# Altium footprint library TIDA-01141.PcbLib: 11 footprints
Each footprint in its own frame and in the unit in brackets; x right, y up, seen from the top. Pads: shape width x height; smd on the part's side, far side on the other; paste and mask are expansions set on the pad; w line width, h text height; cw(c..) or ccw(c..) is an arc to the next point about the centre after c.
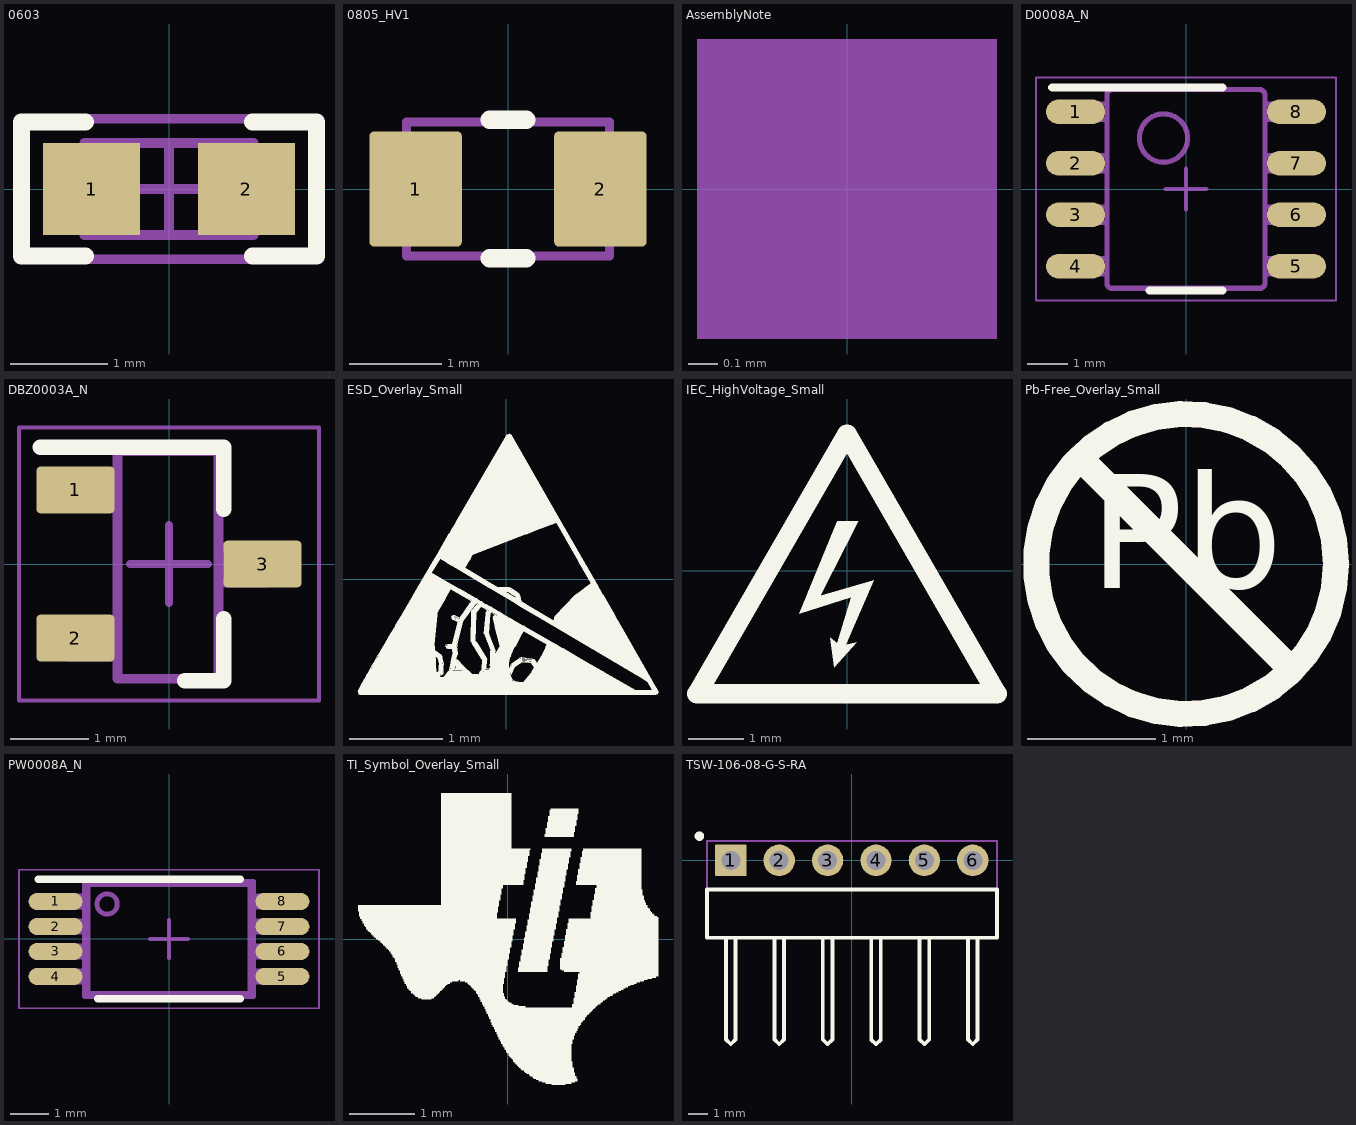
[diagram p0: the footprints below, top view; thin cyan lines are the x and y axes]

## 0603 [mm] "0603 from SM-752 data"
height 1
pads (2):
  rect 1x0.95 smd: 1(-0.8,0) 2(0.8,0)
Top Overlay:
  lines w0.178: -0.864,-0.691 -1.524,-0.691 -1.524,0.693 -0.864,0.693 ; 0.864,-0.691 1.524,-0.691 1.524,0.693 0.864,0.693
Mechanical 5:
  lines w0.1: -1.55,-0.725 -1.55,0.725 1.55,0.725 1.55,-0.725 -1.55,-0.725
  text ".Designator" at -0.559,-0.356 h0.76
Mechanical 13:
  lines w0.1: -0.55,-0.475 -0.55,0.475 ; 0.55,-0.475 0.55,0.475 ; -0.875,-0.475 0.875,-0.475 0.875,0.475 -0.875,0.475 -0.875,-0.475
Mechanical 15:
  lines w0.1: -0.475,0 0.475,0 ; 0,-0.475 0,0.475 ; -1.55,-0.725 1.55,-0.725 1.55,0.725 -1.55,0.725 -1.55,-0.725
3D body: height 1, standoff 0, extent -0.874,-0.474 -0.551,0.474
3D body: height 1, standoff 0, extent -0.549,-0.474 0.549,0.474
3D body: height 1, standoff 0, extent 0.551,-0.474 0.874,0.474

## 0805_HV1 [mm] "Custom footprint based on analyzing multiple manufacturer recommendations"
height 1.45
pads (2):
  rrect10% 1x1.25 smd: 1(-1,0) 2(1,0)
Top Overlay:
  lines w0.2: -0.2,-0.75 0.2,-0.75 ; -0.2,0.75 0.2,0.75
Mechanical 5:
  lines w0.1: -1.1,-0.725 1.1,-0.725 1.1,0.725 -1.1,0.725 -1.1,-0.725
  text ".Designator" at -0.737,-0.381 h0.76
3D body: height 1.45, standoff 0, extent -1.1,-0.725 1.1,0.725

## AssemblyNote [mm] "Assembly Note"
Mechanical 5:
  rectangle: -0.508,-0.508 0.508,0.508
  text ".Designator" at -4.191,-0.508 h1.02
  text ".Comment" at 1.143,-0.508 h1.02

## D0008A_N [mm] "SOIC, 8-Leads, Body 4.9x3.9mm, Pitch 1.27mm, IPC Medium Density"
height 1.75
pads (8):
  oval 1.45x0.6 smd: 1(-2.725,1.905) 2(-2.725,0.635) 3(-2.725,-0.635) 4(-2.725,-1.905) 5(2.725,-1.905) 6(2.725,-0.635) 7(2.725,0.635) 8(2.725,1.905)
Top Overlay:
  lines w0.2: -3.3,2.5 0.9,2.5 ; -0.9,-2.5 0.9,-2.5
Mechanical 5:
  lines w0.127: -2.375,-2.095 -1.995,-2.095 -1.952,-2.095 -1.952,-1.715 -1.995,-1.715 -2.375,-1.715 ; -2.375,-2.095 -2.589,-2.095 -3.002,-2.095 -3.002,-1.715 -2.589,-1.715 -2.375,-1.715 ; -2.375,-2.095 -2.375,-1.715 ; -2.375,-0.825 -1.995,-0.825 -1.952,-0.825 -1.952,-0.445 -1.995,-0.445 -2.375,-0.445 ; -2.375,-0.825 -2.589,-0.825 -3.002,-0.825 -3.002,-0.445 -2.589,-0.445 -2.375,-0.445 ; -2.375,-0.825 -2.375,-0.445 ; -2.375,0.445 -1.995,0.445 -1.952,0.445 -1.952,0.825 -1.995,0.825 -2.375,0.825 ; -2.375,0.445 -2.589,0.445 -3.002,0.445 -3.002,0.825 -2.589,0.825 -2.375,0.825 ; -2.375,0.445 -2.375,0.825 ; -2.375,1.715 -1.995,1.715 -1.952,1.715 -1.952,2.095 -1.995,2.095 -2.375,2.095 ; -2.375,1.715 -2.589,1.715 -3.002,1.715 -3.002,2.095 -2.589,2.095 -2.375,2.095 ; -2.375,1.715 -2.375,2.095 ; -0.332,-2.45 -1.825,-2.45 -1.826,-2.45 cw(c-1.825,-2.323) -1.952,-2.324 -1.952,-2.323 -1.952,2.323 -1.952,2.324 cw(c-1.825,2.323) -1.826,2.45 -1.825,2.45 -0.332,2.45 ; -0.332,-2.45 -0.182,-2.45 ; -0.332,-2.45 -0.182,-2.45 ; -0.332,2.45 -0.182,2.45 ; -0.332,2.45 -0.182,2.45 ; -0.182,-2.45 0.178,-2.45 ; -0.182,2.45 0.178,2.45 ; 0.178,-2.45 0.328,-2.45 ; 0.178,-2.45 0.328,-2.45 ; 0.178,2.45 0.328,2.45 ; 0.178,2.45 0.328,2.45 ; 0.328,-2.45 1.821,-2.45 1.822,-2.45 ccw(c1.821,-2.323) 1.948,-2.324 1.948,-2.323 1.948,2.323 1.948,2.324 ccw(c1.821,2.323) 1.822,2.45 1.821,2.45 0.328,2.45 ; 2.371,-2.095 2.585,-2.095 2.998,-2.095 2.998,-1.715 2.585,-1.715 2.371,-1.715 ; 2.371,-2.095 1.991,-2.095 1.948,-2.095 1.948,-1.715 1.991,-1.715 2.371,-1.715 ; 2.371,-2.095 2.371,-1.715 ; 2.371,-0.825 2.585,-0.825 2.998,-0.825 2.998,-0.445 2.585,-0.445 2.371,-0.445 ; 2.371,-0.825 1.991,-0.825 1.948,-0.825 1.948,-0.445 1.991,-0.445 2.371,-0.445 ; 2.371,-0.825 2.371,-0.445 ; 2.371,0.445 2.585,0.445 2.998,0.445 2.998,0.825 2.585,0.825 2.371,0.825 ; 2.371,0.445 1.991,0.445 1.948,0.445 1.948,0.825 1.991,0.825 2.371,0.825 ; 2.371,0.445 2.371,0.825 ; 2.371,1.715 2.585,1.715 2.998,1.715 2.998,2.095 2.585,2.095 2.371,2.095 ; 2.371,1.715 1.991,1.715 1.948,1.715 1.948,2.095 1.991,2.095 2.371,2.095 ; 2.371,1.715 2.371,2.095 ; -0.555,0.659 cw(c-0.555,1.256) -0.555,1.853 cw(c-0.555,1.256) -0.555,0.659
  text ".Designator" at 0.305,-1.27 h0.76
Mechanical 15:
  lines w0.05: -3.7,-2.75 3.7,-2.75 3.7,2.75 -3.7,2.75 -3.7,-2.75
  lines w0.1: -0.5,0 0.5,0 ; 0,-0.5 0,0.5
3D body: height 1.63, standoff 0, extent -3,-2.45 3,2.45

## DBZ0003A_N [mm] "SOT23, 3-Leads, Body 2.9x1.3mm, Pitch 0.95mm, Lead Span 2.4mm, IPC Medium Density"
height 1.12
pads (3):
  rrect17% 1x0.6 smd: 1(-1.2,0.95) 2(-1.2,-0.95) 3(1.2,0)
Top Overlay:
  lines w0.2: -1.651,1.5 0.7,1.5 0.7,0.7 ; 0.2,-1.5 0.7,-1.5 0.7,-0.7
Mechanical 5:
  lines w0.127: -1.27,-1.187 -1.27,-0.743 -1.063,-0.743 -1.005,-0.743 -0.814,-0.743 -0.66,-0.743 -0.66,-1.187 -0.814,-1.187 -1.005,-1.187 -1.063,-1.187 -1.27,-1.187 ; -1.27,0.718 -1.27,1.162 -1.063,1.162 -1.005,1.162 -0.814,1.162 -0.66,1.162 -0.66,0.718 -0.814,0.718 -1.005,0.718 -1.063,0.718 -1.27,0.718 ; -0.66,-1.473 -0.66,1.448 0.635,1.448 0.635,-1.473 -0.66,-1.473 ; 0.635,-0.235 0.789,-0.235 0.98,-0.235 1.037,-0.235 1.245,-0.235 1.245,0.21 1.037,0.21 0.98,0.21 0.789,0.21 0.635,0.21 0.635,-0.235
  text ".Designator" at -0.432,0.711 h0.76
Mechanical 15:
  lines w0.05: -1.925,-1.75 1.925,-1.75 1.925,1.75 -1.925,1.75 -1.925,-1.75
  lines w0.1: -0.5,0 0.5,0 ; 0,-0.5 0,0.5
3D body: height 0.98, standoff 0, extent -1.257,-1.461 1.258,1.461

## ESD_Overlay_Small [mm]
height 0.33
Top Overlay:
  drawing of 901 lines, arcs and shapes, not listed

## IEC_HighVoltage_Small [mm]
height 0.33
Top Overlay:
  region: -0.178,0.889 0.203,0.889 -0.483,-0.457 0.483,-0.178 -0.025,-1.346 0.178,-1.295 -0.229,-1.753 -0.305,-1.219 -0.178,-1.321 0.076,-0.483 -0.864,-0.787
  lines w0.356: -2.718,-2.235 0,2.472 2.718,-2.235 -2.718,-2.235

## Pb-Free_Overlay_Small [mm]
Top Overlay:
  circle w0.203: c0,0 r1.168
  lines w0.203: -0.826,0.826 0.826,-0.826
  text "Pb" at -0.752,-0.48 h1.52

## PW0008A_N [mm] "TSOP, 8-Leads, Body 3x4.4mm, Pitch 0.65mm, IPC Medium Density"
height 1.2
pads (8):
  oval 1.4x0.45 smd: 1(-2.95,0.975) 2(-2.95,0.325) 3(-2.95,-0.325) 4(-2.95,-0.975) 5(2.95,-0.975) 6(2.95,-0.325) 7(2.95,0.325) 8(2.95,0.975)
Top Overlay:
  lines w0.2: -3.4,1.55 1.85,1.55 ; -1.85,-1.55 1.85,-1.55
Mechanical 5:
  lines w0.127: -2.2,-1.5 -2.2,-1.125 ; -2.2,-1.5 2.2,-1.5 ; -2.2,-1.5 -2.11,-1.41 ; -2.2,-1.125 -2.4,-1.125 -2.669,-1.125 -2.785,-1.125 -2.856,-1.125 -3.228,-1.125 -3.228,-0.825 -2.856,-0.825 -2.785,-0.825 -2.669,-0.825 -2.4,-0.825 -2.2,-0.825 ; -2.2,-1.125 -2.2,-0.825 ; -2.2,-0.825 -2.2,-0.475 ; -2.2,-0.475 -2.2,-0.175 ; -2.2,-0.475 -2.4,-0.475 -2.669,-0.475 -2.785,-0.475 -2.856,-0.475 -3.228,-0.475 -3.228,-0.175 -2.856,-0.175 -2.785,-0.175 -2.669,-0.175 -2.4,-0.175 -2.2,-0.175 ; -2.2,-0.175 -2.2,0.175 ; -2.2,0.175 -2.4,0.175 -2.669,0.175 -2.785,0.175 -2.856,0.175 -3.228,0.175 -3.228,0.475 -2.856,0.475 -2.785,0.475 -2.669,0.475 -2.4,0.475 -2.2,0.475 ; -2.2,0.175 -2.2,0.475 ; -2.2,0.475 -2.2,0.825 ; -2.2,0.825 -2.2,1.125 ; -2.2,0.825 -2.4,0.825 -2.669,0.825 -2.785,0.825 -2.856,0.825 -3.228,0.825 -3.228,1.125 -2.856,1.125 -2.785,1.125 -2.669,1.125 -2.4,1.125 -2.2,1.125 ; -2.2,1.125 -2.2,1.5 ; -2.2,1.5 2.2,1.5 ; -2.2,1.5 -2.11,1.41 ; -2.11,-1.41 2.11,-1.41 ; -2.11,-1.41 -2.11,1.41 ; -2.11,1.41 2.11,1.41 ; 2.11,-1.41 2.2,-1.5 ; 2.11,-1.41 2.11,1.41 ; 2.11,1.41 2.2,1.5 ; 2.2,-1.5 2.2,-1.125 ; 2.2,-1.125 2.4,-1.125 2.669,-1.125 2.785,-1.125 2.856,-1.125 3.228,-1.125 3.228,-0.825 2.856,-0.825 2.785,-0.825 2.669,-0.825 2.4,-0.825 2.2,-0.825 ; 2.2,-1.125 2.2,-0.825 ; 2.2,-0.825 2.2,-0.475 ; 2.2,-0.475 2.4,-0.475 2.669,-0.475 2.785,-0.475 2.856,-0.475 3.228,-0.475 3.228,-0.175 2.856,-0.175 2.785,-0.175 2.669,-0.175 2.4,-0.175 2.2,-0.175 ; 2.2,-0.475 2.2,-0.175 ; 2.2,-0.175 2.2,0.175 ; 2.2,0.175 2.2,0.475 ; 2.2,0.175 2.4,0.175 2.669,0.175 2.785,0.175 2.856,0.175 3.228,0.175 3.228,0.475 2.856,0.475 2.785,0.475 2.669,0.475 2.4,0.475 2.2,0.475 ; 2.2,0.475 2.2,0.825 ; 2.2,0.825 2.2,1.125 ; 2.2,0.825 2.4,0.825 2.669,0.825 2.785,0.825 2.856,0.825 3.228,0.825 3.228,1.125 2.856,1.125 2.785,1.125 2.669,1.125 2.4,1.125 2.2,1.125 ; 2.2,1.125 2.2,1.5 ; -1.61,0.646 ccw(c-1.61,0.91) -1.61,1.173 ccw(c-1.61,0.91) -1.61,0.646
  text ".Designator" at -0.457,-0.381 h0.76
Mechanical 15:
  lines w0.05: -3.9,-1.8 3.9,-1.8 3.9,1.8 -3.9,1.8 -3.9,-1.8
  lines w0.1: -0.5,0 0.5,0 ; 0,-0.5 0,0.5
3D body: height 1.2, standoff 0, extent -3.208,-1.5 3.208,1.5

## TI_Symbol_Overlay_Small [mm]
Top Overlay:
  drawing of 3 lines, arcs and shapes, not listed

## TSW-106-08-G-S-RA [mm] "Samtec Right Angle Header"
height 2.794
pads (6):
  rrect6% 1.65x1.65 hole 1: 1(-6.35,0)
  round 1.65 hole 1: 2(-3.81,0) 3(-1.27,0) 4(1.27,0) 5(3.81,0) 6(6.35,0)
Top Overlay:
  circle w0.25: c-7.999,1.27 r0.125
  lines w0.2: -6.604,-4.064 -6.604,-9.398 -6.35,-9.652 -6.096,-9.398 -6.096,-4.064 ; -4.064,-4.064 -4.064,-9.398 -3.81,-9.652 -3.556,-9.398 -3.556,-4.064 ; -1.524,-4.064 -1.524,-9.398 -1.27,-9.652 -1.016,-9.398 -1.016,-4.064 ; 1.016,-4.064 1.016,-9.398 1.27,-9.652 1.524,-9.398 1.524,-4.064 ; 3.556,-4.064 3.556,-9.398 3.81,-9.652 4.064,-9.398 4.064,-4.064 ; 6.096,-4.064 6.096,-9.398 6.35,-9.652 6.604,-9.398 6.604,-4.064 ; -7.6,-4.064 7.62,-4.064 7.62,-1.524 -7.6,-1.524 -7.6,-4.064
Mechanical 5:
  lines w0.127: -6.604,-4.064 -6.604,-9.398 -6.35,-9.652 -6.096,-9.398 -6.096,-4.064 ; -4.064,-4.064 -4.064,-9.398 -3.81,-9.652 -3.556,-9.398 ; -1.524,-4.064 -1.524,-9.398 -1.27,-9.652 -1.016,-9.398 ; 1.016,-4.064 1.016,-9.398 1.27,-9.652 1.524,-9.398 ; 3.556,-4.064 3.556,-9.398 3.81,-9.652 4.064,-9.398 ; 6.096,-4.064 6.096,-9.398 6.35,-9.652 6.604,-9.398 ; -3.556,-9.398 -3.556,-4.064 -3.556,-9.398 ; -1.016,-9.398 -1.016,-4.064 -1.016,-9.398 ; 1.524,-9.398 1.524,-4.064 1.524,-9.398 ; 4.064,-9.398 4.064,-4.064 4.064,-9.398 ; 6.604,-9.398 6.604,-4.064 6.604,-9.398 ; -7.6,-4.064 -7.6,1.016 7.62,1.016 7.62,-4.064 -7.6,-4.064
  text ".Designator" at -0.432,-2.159 h0.76
3D body: height 3.05, standoff -2.29, extent -7.62,-9.906 7.62,0.318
